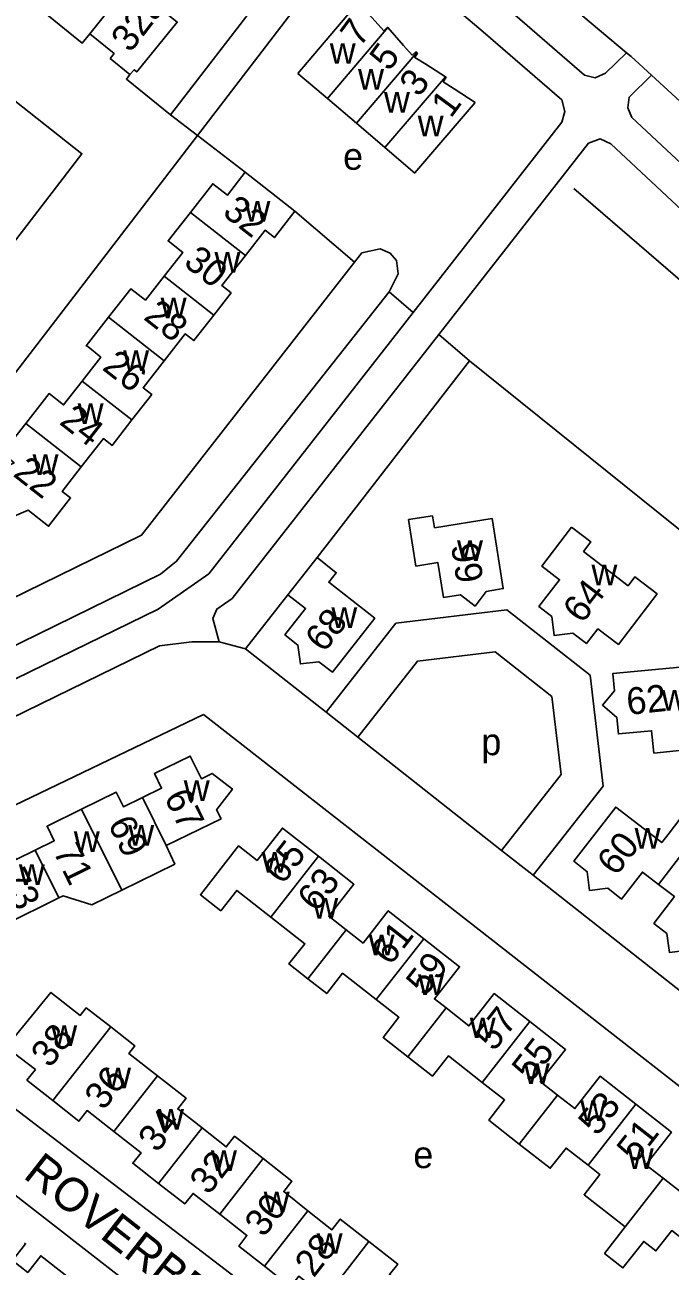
# Model space of a CAD drawing. Extents: x 159441 to 162086, y 388175 to 389787.
# Drawn here: x 161598.1 to 161694.2, y 388970.9 to 389155.6 of the extents above; entities that cross this region are included whole.
import ezdxf

# ---------------------------------------------------------------- set-up
doc = ezdxf.new("R2010")
doc.units = 0
for name, color, linetype in [('BLT_Basislijn', 7, 'Continuous'), ('BLT_Bebouwing', 7, 'Continuous'), ('BLT_Centroide', 7, 'Continuous'), ('BLT_Huisnummer', 7, 'Continuous'), ('BLT_Huisnummer_ tussenligend', 7, 'Continuous'), ('BLT_Onderverdeling_panden', 7, 'Continuous'), ('BLT_Straatnaam', 7, 'Continuous')]:
    doc.layers.add(name, color=color, linetype=linetype)

msp = doc.modelspace()

# ---------------------------------------------------------------- linework, layer by layer
at = {"layer": 'BLT_Basislijn'}
for p, q in [((161619.81, 389142.15), (161643.91, 389173.47)), ((161623.83, 389139.1), (161647.75, 389170.26)), ((161684.6, 389148.34), (161687.69, 389151.41)), ((161688.1, 389144.77), (161691.41, 389148.05)), ((161619.81, 389142.15), (161623.83, 389139.1)), ((161630.93, 389133.61), (161623.83, 389139.1)), ((161642.97, 389053.27), (161647.68, 389049.57)), ((161564.11, 389023.88), (161624.74, 389052.92)), ((161624.74, 389052.92), (161725.16, 388974.48)), ((161669.11, 389032.72), (161673.83, 389029.02)), ((161669.17, 388938.91), (161567.55, 389016.49)), ((161661.19, 388931.3), (161556.12, 389012.95))]:
    msp.add_line(p, q, dxfattribs=at)
for points in [[(161654.61, 389179.2), (161687.69, 389151.41)], [(161650.8, 389174.23), (161669.59, 389158.32), (161681.47, 389148.08), (161683.06, 389147.69), (161684.6, 389148.34)], [(161647.75, 389170.26), (161666.35, 389154.52), (161678.07, 389144.41), (161678.54, 389142.65), (161678.08, 389141.05)], [(161593.69, 389163.33), (161606.65, 389152.82), (161607.8, 389154.23)], [(161596.3, 389122.92), (161606.62, 389136.37), (161585.4, 389153.05), (161582.29, 389151.56)], [(161687.69, 389151.41), (161688.38, 389150.84), (161691.41, 389148.05)], [(161613.77, 389148.14), (161613.24, 389147.48), (161619.81, 389142.15)], [(161691.41, 389148.05), (161735.72, 389107.41), (161753.21, 389088.75), (161766.25, 389072.05), (161798.02, 389027.59), (161806.06, 389014.52)], [(161688.1, 389144.77), (161687.91, 389143.2), (161688.52, 389141.77), (161734.25, 389099.09), (161753.44, 389078.28), (161784.28, 389041.3), (161806.06, 389014.52)], [(161678.08, 389141.05), (161655.94, 389112.75)], [(161623.83, 389139.1), (161595.65, 389102.37), (161475.36, 389042.81), (161487.87, 389017.18)], [(161682.02, 389137.97), (161683.78, 389138.6), (161685.37, 389137.87), (161730.7, 389095.56), (161749.68, 389074.98), (161780.42, 389038.13), (161801.97, 389011.62)], [(161682.02, 389137.97), (161659.74, 389109.49)], [(161679.84, 389131.19), (161712.26, 389103.29), (161753.04, 389062.36), (161790.08, 389020.85)], [(161647.2, 389120.24), (161638.34, 389127.83)], [(161652.36, 389115.82), (161653.7, 389118.48), (161653.45, 389120.48), (161652.53, 389121.57), (161651.05, 389122.22), (161648.28, 389121.62), (161647.2, 389120.24)], [(161647.2, 389120.24), (161615.5, 389079.64), (161487.87, 389017.18)], [(161490.89, 389011.37), (161618.3, 389073.8), (161620.71, 389075.73), (161652.36, 389115.82)], [(161655.94, 389112.75), (161652.36, 389115.82)], [(161655.94, 389112.75), (161625.53, 389073.89), (161617.95, 389068.61), (161492.72, 389007.49)], [(161659.74, 389109.49), (161629, 389070.21), (161626.71, 389068.61), (161626.1, 389067.21), (161627.07, 389063.74)], [(161664.32, 389105.57), (161659.74, 389109.49)], [(161641.63, 389076.28), (161664.32, 389105.57)], [(161820.56, 388933.37), (161795.51, 388978.78), (161751.61, 389035.42), (161664.32, 389105.57)], [(161630.97, 389062.7), (161637.3, 389070.75)], [(161642.97, 389053.27), (161653.38, 389066.52), (161669.89, 389068.5), (161682.27, 389058.77), (161684.24, 389042.27), (161673.83, 389029.02)], [(161618.18, 389063.15), (161493.93, 389002.52)], [(161618.18, 389063.15), (161623, 389063.76), (161627.07, 389063.74)], [(161627.07, 389063.74), (161630.97, 389062.7)], [(161630.97, 389062.7), (161642.97, 389053.27)], [(161669.11, 389032.72), (161677.99, 389044.02), (161676.6, 389055.59), (161668.14, 389062.25), (161656.56, 389060.86), (161647.68, 389049.57)], [(161647.68, 389049.57), (161669.11, 389032.72)], [(161673.83, 389029.02), (161698.33, 389009.76)]]:
    msp.add_lwpolyline(points, dxfattribs=at)
at = {"layer": 'BLT_Bebouwing'}
msp.add_line((161603.18, 389025.66), (161595.17, 389021.68), dxfattribs=at)
for points in [[(161607.8, 389154.23), (161613.76, 389161.71), (161620.81, 389155.95), (161614.79, 389148.55), (161614.38, 389148.88), (161613.77, 389148.14)], [(161638.77, 389148.33), (161647.77, 389158.9), (161650.27, 389156.11), (161651.56, 389154.67), (161652.13, 389155.2), (161652.18, 389155.14)], [(161652.18, 389155.14), (161654.52, 389152.49), (161655.79, 389151.04), (161656.35, 389151.53), (161656.49, 389151.46)], [(161610.82, 389150.54), (161611.42, 389151.28), (161607.8, 389154.23)], [(161656.49, 389151.46), (161656.58, 389151.33), (161656.18, 389150.69), (161657.8, 389149.68), (161660.73, 389147.84)], [(161613.77, 389148.14), (161610.82, 389150.54)], [(161643.17, 389144.58), (161638.77, 389148.33)], [(161660.73, 389147.84), (161660.85, 389147.76), (161660.42, 389147.09), (161662.03, 389146.05), (161665.18, 389144)], [(161647.48, 389140.9), (161643.17, 389144.58)], [(161665.18, 389144), (161656.21, 389133.54), (161656.17, 389133.49), (161651.72, 389137.28)], [(161651.72, 389137.28), (161647.48, 389140.9)], [(161622.77, 389127.64), (161626.1, 389131.9), (161628.27, 389130.2), (161630.93, 389133.61)], [(161630.93, 389133.61), (161638.34, 389127.83)], [(161618.85, 389118.15), (161621.62, 389121.69), (161619.45, 389123.39), (161622.77, 389127.64)], [(161638.34, 389127.83), (161635.27, 389123.9), (161633.89, 389124.98), (161630.97, 389121.24)], [(161630.97, 389121.24), (161627.46, 389116.75), (161628.84, 389115.67), (161626.25, 389112.36)], [(161610.58, 389112.04), (161613.91, 389116.29), (161616.08, 389114.6), (161618.85, 389118.15)], [(161626.25, 389112.36), (161623.3, 389108.58), (161622, 389109.59), (161618.86, 389105.57)], [(161606.65, 389102.55), (161609.43, 389106.09), (161607.5, 389107.71), (161607.26, 389107.78), (161610.58, 389112.04)], [(161618.86, 389105.57), (161615.72, 389101.55), (161617.02, 389100.54), (161614.06, 389096.76)], [(161598.25, 389096.25), (161601.72, 389100.69), (161603.88, 389099), (161606.65, 389102.55)], [(161592.32, 389088.29), (161596.53, 389090.37), (161594.78, 389091.81), (161598.25, 389096.25)], [(161614.06, 389096.76), (161611.11, 389092.98), (161609.81, 389093.99), (161606.52, 389089.79)], [(161606.52, 389089.79), (161603.67, 389086.14), (161604.94, 389085.15), (161601.66, 389080.95), (161598.62, 389083.33), (161595.4, 389081.97)], [(161658.84, 389082.5), (161659.12, 389080.73), (161667.71, 389082.08), (161669.35, 389071.66), (161666.81, 389071.26), (161665.15, 389069.06), (161662.99, 389070.73), (161660.44, 389070.36), (161659.63, 389075.53), (161656.35, 389075.02), (161655.26, 389081.94), (161658.84, 389082.5)], [(161679.52, 389080.83), (161682.4, 389078.62), (161681.31, 389077.19), (161687.95, 389072.1), (161688.94, 389073.4), (161692.25, 389070.87), (161686.49, 389063.36), (161683.44, 389065.7), (161681.74, 389063.48), (161679.69, 389065.05), (161676.93, 389064.71), (161676.59, 389067.5), (161674.65, 389069.01), (161677.74, 389072.99), (161675.1, 389074.99), (161679.52, 389080.83)], [(161641.63, 389076.28), (161644.49, 389074.03), (161643.38, 389072.62), (161650.21, 389067.26), (161643.91, 389059.23), (161641.9, 389060.79), (161639.14, 389060.46), (161638.79, 389063.26), (161636.85, 389064.79), (161639.92, 389068.7), (161637.3, 389070.75)], [(161637.3, 389070.75), (161641.63, 389076.28)], [(161695.7, 389060), (161696.59, 389051.37), (161701.37, 389051.86), (161701.74, 389048.23), (161691.79, 389047.2), (161691.44, 389050.52), (161686.51, 389050.05), (161686.26, 389052.49), (161684.11, 389054.33), (161685.9, 389056.47), (161685.65, 389059.02), (161695.7, 389060)], [(161615.64, 389040.59), (161618.47, 389041.97), (161617.41, 389044.14), (161622.74, 389046.74), (161624.4, 389043.38), (161626.02, 389044.17), (161629.02, 389041.83), (161626.67, 389038.77), (161627.33, 389037.42), (161619.18, 389033.43)], [(161606.58, 389038.84), (161611.73, 389041.37), (161612.8, 389039.2), (161615.64, 389040.59)], [(161599.66, 389032.76), (161602.49, 389034.16), (161601.43, 389036.31), (161606.58, 389038.84)], [(161692.46, 389027.66), (161690.07, 389029.49), (161686.97, 389025.46), (161684.94, 389027.08), (161682.21, 389026.76), (161681.85, 389029.53), (161679.87, 389031.1), (161686.09, 389039.15), (161692.94, 389033.88), (161694.05, 389035.29), (161695.65, 389037.34), (161698.31, 389035.26), (161696.71, 389033.22)], [(161634.74, 389022.79), (161629.67, 389026.76), (161627.3, 389023.73), (161624.26, 389026.11), (161629.95, 389033.37), (161632.7, 389031.22), (161636.46, 389036.03), (161641.82, 389031.84)], [(161590.61, 389031), (161595.76, 389033.53), (161596.83, 389031.37), (161599.66, 389032.76)], [(161619.18, 389033.43), (161620.45, 389030.69), (161612.54, 389026.82)], [(161696.71, 389033.22), (161699.39, 389031.12), (161698.28, 389029.71), (161705.12, 389024.35), (161698.84, 389016.32), (161696.85, 389017.88), (161694.08, 389017.53), (161693.73, 389020.33), (161691.78, 389021.86), (161694.84, 389025.84), (161692.46, 389027.66)], [(161641.82, 389031.84), (161647.12, 389027.69), (161643.38, 389022.92), (161645.96, 389020.9)], [(161612.54, 389026.82), (161608.1, 389024.64), (161603.82, 389025.97), (161603.18, 389025.66)], [(161645.96, 389020.9), (161648.48, 389018.93), (161652.23, 389023.72), (161657.54, 389019.56)], [(161640.26, 389013.62), (161637.45, 389015.82), (161639.81, 389018.83), (161634.74, 389022.79)], [(161657.54, 389019.56), (161662.85, 389015.41), (161659.11, 389010.62), (161660.83, 389009.27)], [(161650.45, 389010.51), (161645.43, 389014.44), (161643.07, 389011.42), (161640.26, 389013.62)], [(161602.29, 388995.48), (161598.42, 388998.53), (161599.7, 389000.09), (161595.32, 389003.42), (161602, 389011.58), (161606.38, 389008.15), (161607.25, 389009.27), (161610.91, 389006.44)], [(161660.83, 389009.27), (161664.25, 389006.6), (161668.01, 389011.4), (161673.31, 389007.24)], [(161655.14, 389002), (161651.46, 389004.88), (161653.81, 389007.88), (161650.45, 389010.51)], [(161673.31, 389007.24), (161678.62, 389003.09), (161674.87, 388998.31), (161677.44, 388996.3)], [(161610.91, 389006.44), (161614.49, 389003.64), (161613.59, 389002.5), (161617.86, 388999.16)], [(161666.23, 388998.19), (161661.18, 389002.14), (161658.81, 388999.13), (161655.14, 389002)], [(161617.86, 388999.16), (161622.12, 388995.83), (161620.89, 388994.25), (161624.5, 388991.43)], [(161671.74, 388989.02), (161667.18, 388992.59), (161669.54, 388995.6), (161666.23, 388998.19)], [(161677.44, 388996.3), (161680.01, 388994.29), (161683.77, 388999.1), (161689.08, 388994.94)], [(161611.39, 388990.9), (161607.4, 388994.01), (161606.17, 388992.43), (161602.29, 388995.48)], [(161689.08, 388994.94), (161694.39, 388990.78), (161690.6, 388985.94), (161693.16, 388983.94)], [(161618.03, 388983.16), (161614.19, 388986.17), (161615.43, 388987.74), (161611.39, 388990.9)], [(161624.5, 388991.43), (161628.11, 388988.6), (161629.36, 388990.18), (161633.61, 388986.85)], [(161681.98, 388985.87), (161678.71, 388988.43), (161676.34, 388985.42), (161671.74, 388989.02)], [(161633.61, 388986.85), (161637.88, 388983.49), (161636.68, 388981.94), (161640.24, 388979.11)], [(161693.16, 388983.94), (161695.71, 388981.94), (161699.49, 388986.77), (161704.81, 388982.61)], [(161687.49, 388976.71), (161681.38, 388981.49), (161683.73, 388984.5), (161681.98, 388985.87)], [(161627.13, 388978.59), (161623.16, 388981.68), (161621.93, 388980.11), (161618.03, 388983.16)], [(161633.78, 388970.85), (161629.96, 388973.85), (161631.19, 388975.42), (161627.13, 388978.59)], [(161640.24, 388979.11), (161643.85, 388976.28), (161645.08, 388977.85), (161649.36, 388974.5)], [(161697.73, 388973.56), (161694.44, 388976.14), (161692.08, 388973.12), (161690.26, 388974.54), (161687.18, 388970.6), (161684.43, 388972.75), (161687.49, 388976.71)], [(161605.96, 388968.13), (161600.5, 388972.39), (161598.56, 388969.92), (161596.29, 388971.71), (161598.23, 388974.18), (161598.09, 388974.3)], [(161649.36, 388974.5), (161653.64, 388971.15), (161652.41, 388969.61), (161656.02, 388966.75)], [(161642.9, 388966.24), (161638.92, 388969.37), (161637.68, 388967.8), (161633.78, 388970.85)]]:
    msp.add_lwpolyline(points, dxfattribs=at)
at = {"layer": 'BLT_Onderverdeling_panden'}
for p, q in [((161622.77, 389127.64), (161630.97, 389121.24)), ((161618.85, 389118.15), (161626.25, 389112.36)), ((161610.58, 389112.04), (161618.86, 389105.57)), ((161606.65, 389102.55), (161614.06, 389096.76)), ((161598.25, 389096.25), (161606.52, 389089.79)), ((161615.64, 389040.59), (161619.18, 389033.43)), ((161606.58, 389038.84), (161612.54, 389026.82)), ((161692.46, 389027.66), (161696.71, 389033.22)), ((161599.66, 389032.76), (161603.18, 389025.66)), ((161634.74, 389022.79), (161641.82, 389031.84)), ((161640.26, 389013.62), (161645.96, 389020.9)), ((161657.54, 389019.56), (161650.45, 389010.51)), ((161655.14, 389002), (161660.83, 389009.27)), ((161673.31, 389007.24), (161666.23, 388998.19)), ((161602.29, 388995.48), (161610.91, 389006.44)), ((161617.86, 388999.16), (161611.39, 388990.9)), ((161677.44, 388996.3), (161671.74, 388989.02)), ((161689.08, 388994.94), (161681.98, 388985.87)), ((161624.5, 388991.43), (161618.03, 388983.16)), ((161633.61, 388986.85), (161627.13, 388978.59)), ((161693.16, 388983.94), (161687.49, 388976.71)), ((161640.24, 388979.11), (161633.78, 388970.85)), ((161649.36, 388974.5), (161642.9, 388966.24))]:
    msp.add_line(p, q, dxfattribs=at)
for points in [[(161643.17, 389144.58), (161652.18, 389155.14)], [(161656.49, 389151.46), (161647.48, 389140.9)], [(161660.73, 389147.84), (161651.72, 389137.28)]]:
    msp.add_lwpolyline(points, dxfattribs=at)

# ---------------------------------------------------------------- texts
at = {"layer": 'BLT_Centroide'}
for s, p in [('w', (161643.52, 389149.75)), ('w', (161647.73, 389145.89)), ('w', (161651.59, 389142.49)), ('w', (161656.61, 389138.98)), ('e', (161645.51, 389133.99)), ('w', (161630.82, 389126.28)), ('w', (161626.36, 389118.67)), ('w', (161618.34, 389111.88)), ('w', (161612.75, 389104.06)), ('w', (161605.98, 389096.16)), ('w', (161599.27, 389088.59)), ('w', (161662.47, 389075.78)), ('w', (161682.48, 389072.16)), ('w', (161643.75, 389065.83)), ('w', (161692.92, 389053.52)), ('p', (161666.09, 389046.88)), ('w', (161621.78, 389040.06)), ('w', (161605.41, 389032.47)), ('w', (161613.52, 389033.44)), ('w', (161688.91, 389032.97)), ('w', (161633.38, 389029.41)), ('w', (161597.23, 389027.59)), ('w', (161640.92, 389022.58)), ('w', (161649.31, 389017.12)), ('w', (161656.66, 389011.19)), ('w', (161664.36, 389004.78)), ('w', (161602.05, 389003.61)), ('w', (161610.07, 388997.31)), ('w', (161672.42, 388997.98)), ('w', (161617.94, 388991.16)), ('w', (161680.8, 388992.47)), ('e', (161655.96, 388985.44)), ('w', (161625.83, 388985)), ('w', (161687.89, 388985.31)), ('w', (161633.69, 388978.86)), ('w', (161641.57, 388972.69))]:
    msp.add_text(s, height=4, dxfattribs=at).set_placement(p)
at = {"layer": 'BLT_Huisnummer'}
for s, rotation, p in [('32a', 52.2031, (161613.81, 389151.27)), ('7', 53.5619, (161648.01, 389152.09)), ('5', 53.5619, (161652.36, 389148.5)), ('1', 53.5619, (161661.54, 389141.53)), ('32', 322.0058, (161627.38, 389127.36)), ('26', 322.0058, (161609.48, 389104.35)), ('22', 322.0058, (161596.21, 389088.52)), ('66', 98.9602, (161666.43, 389072.87)), ('64', 52.5084, (161681.1, 389066.31)), ('68', 51.8797, (161642.68, 389062)), ('62', 5.9362, (161687.9, 389052.86)), ('67', 296.0725, (161618.79, 389040.66)), ('60', 51.9868, (161686.14, 389028.74)), ('71', 296.0725, (161602.27, 389032.58)), ('65', 51.9499, (161636.5, 389027.48)), ('61', 51.9499, (161652.53, 389015.43)), ('57', 51.9499, (161667.99, 389002.67)), ('38', 51.949, (161601.86, 389000.2)), ('53', 51.9499, (161683.34, 388990.07)), ('34', 51.949, (161617.82, 388987.59)), ('30', 51.949, (161633.67, 388974.99))]:
    msp.add_text(s, height=4, rotation=rotation, dxfattribs=at).set_placement(p)
at = {"layer": 'BLT_Huisnummer_ tussenligend'}
for s, rotation, p in [('3', 53.5619, (161656.81, 389144.65)), ('30', 322.0058, (161621.58, 389119.88)), ('28', 322.0058, (161615.64, 389111.84)), ('24', 322.0058, (161603.1, 389096.26)), ('69', 296.0725, (161610.42, 389036.67)), ('73', 296.0725, (161594.39, 389028.86)), ('63', 51.9499, (161641.54, 389023.38)), ('59', 51.9499, (161657.71, 389010.87)), ('55', 51.9499, (161673.46, 388998.06)), ('36', 51.949, (161609.84, 388993.89)), ('51', 51.9499, (161689.07, 388986.01)), ('32', 51.949, (161625.49, 388981.3)), ('28', 51.949, (161641.13, 388969.01))]:
    msp.add_text(s, height=4, rotation=rotation, dxfattribs=at).set_placement(p)
at = {"layer": 'BLT_Straatnaam'}
msp.add_text('ROVERBRUIDEGOM', height=5, rotation=321.9124, dxfattribs=at).set_placement((161597.71, 388984.12))

doc.saveas('drawing.dxf')
